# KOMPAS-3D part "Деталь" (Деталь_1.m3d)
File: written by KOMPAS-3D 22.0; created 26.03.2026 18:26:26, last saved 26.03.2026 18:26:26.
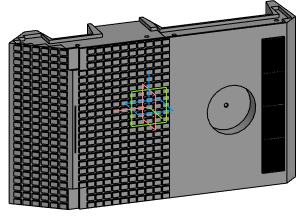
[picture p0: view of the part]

Document properties: Автор: Пользователь Windows; Полное имя файла: F:\Танк\Деталь_1.m3d

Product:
- Part/product: Деталь

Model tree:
1. Операция без истории:1
2. Операция без истории:2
